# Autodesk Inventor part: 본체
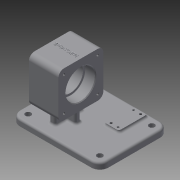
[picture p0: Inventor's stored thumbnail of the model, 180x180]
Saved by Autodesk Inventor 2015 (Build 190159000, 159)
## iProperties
Created: 2019-09
Part Number: 본체
Material: 알루미늄 6061
Document SubType Name: Modeling
Designer: mduedu
Density: 2.71 g/cm^3
Mass: 636.366 g
Surface Area: 520.125 cm^2
Volume: 234.821 cm^3
Appearance: 기본값
Author: mduedu
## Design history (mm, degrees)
sketch "스케치1"
  geometry: L1 (42, -62)-(-84, -62); L2 (-84, -62)-(-84, 36); L3 (-84, 36)-(42, 36); L4 (42, 36)-(42, -62); 1 further point
  constraints: 8 end point, 2 parallel, 1 horizontal, 1 perpendicular
  dimensions: "d0" = 36 distance from line of L3 point (0, 0); "d1" = 98 distance of L1.end L2.end; "d2" = 42 distance from line of L4 point (0, 0); "d3" = 126 distance of L2.end L3.end
extrude "돌출1" new body sketch "스케치1" distance "d4" = 9; taper "d5" = 0 deg
sketch "스케치2"
  geometry: L1 (0, -62)-(0, 36) reference; L2 (27, -32)-(91, -32); L3 (91, -32)-(91, 32); L4 (91, 32)-(27, 32); L5 (27, 32)-(27, -32); L6 (27, -32)-(91, 32); L7 (91, -32)-(27, 32); 3 further points
  constraints: 12 end point, 3 midpoint, 2 parallel, 1 horizontal, 1 horizontal alignment, 1 perpendicular
  dimensions: "d87" = 64 distance of L4.end L3.end; "d88" = 64 distance of L3.end L2.end; "d89" = 59 distance from line of point (59, 0) L1
extrude "돌출2" join sketch "스케치2" stored distance "d8" = 42; taper "d9" = 0 deg
sketch "스케치3"
  geometry: L1 (-17, 4)-(17, 4); L2 (17, 4)-(17, -4); L3 (17, -4)-(-17, -4); L4 (-17, -4)-(-17, 4); L5 (-4, 20)-(4, 20); L6 (4, 20)-(4, -20); L7 (4, -20)-(-4, -20); L8 (-4, -20)-(-4, 20); 5 further points
  constraints: 16 end point, 4 midpoint, 4 parallel, 2 horizontal, 2 horizontal alignment, 2 perpendicular, 2 vertical alignment
  dimensions: "d10" = 8 distance of L5.start L5.end; "d12" = 8 distance of L1.end L2.end; "d13" = 34 distance of L2.end L3.end; "d14" = 40 distance of L5.end L6.end
extrude "돌출3" join sketch "스케치3" stored distance "d15" = 42; taper "d16" = 0 deg
sketch "스케치4"
  geometry: L1 (-32, 91)-(-32, 27) reference; L2 (32, 91)-(-32, 91) reference; L3 (32, 27)-(32, 91) reference; L4 (-32, 27)-(32, 27) reference; C1 r 21 at (0, 59); 3 further points
  constraints: 2 midpoint, 1 centre point, 1 horizontal alignment, 1 vertical alignment
  dimensions: "d17" = 42 diameter of C1
extrude "돌출4" cut sketch "스케치4" distance "d18" = 15; taper "d19" = 0 deg
hole "구멍1" diameter "d22" = 36; stored, may be unused: countersink angle "d26" = 90 deg, drill point angle "d28" = 118 deg; dims "d20" = 10, "d21" = 10, "d23" = 6, "d24" = 4, "d25" = 2, "d27" = 8
fillet "모깎기1" dims "d29" = 0.3
chamfer "모따기1" distance "d30" = 1; stored, may be unused: second distance "d31" = 2, angle "d32" = 45 deg
fillet "모깎기9" dims "d90" = 8
sketch "스케치11"
  geometry: L1 (-24, 27)-(24, 27) reference; L2 (32, 35)-(32, 83) reference; L3 (24, 91)-(-24, 91) reference; L4 (-32, 83)-(-32, 35) reference; C1 r 22 at (0, 59) reference; A1 r 8 centre (-24, 35) between (-32, 35) and (-24, 27) reference; A2 r 8 centre (24, 35) between (24, 27) and (32, 35) reference; A3 r 8 centre (24, 83) between (32, 83) and (24, 91) reference; A4 r 8 centre (-24, 83) between (-24, 91) and (-32, 83) reference; 5 further points
  constraints: 4 coincident
hole "구멍6" sketch "스케치11" at (-24, 83), (24, 83), (24, 35), (-24, 35) diameter "d91" = 3.242; stored, may be unused: countersink angle "d95" = 90 deg, drill point angle "d97" = 118 deg; dims "d92" = 8, "d93" = 4, "d94" = 2, "d96" = 10
fillet "모깎기2" dims "d44" = 12
sketch "스케치6"
  geometry: L1 (-42, 50)-(-42, -24) reference; L2 (-30, -36)-(72, -36) reference; L3 (84, -24)-(84, 50) reference; L4 (72, 62)-(-30, 62) reference; L5 (17, 4)-(17, -4) reference; L6 (17, -4)-(4, -4) reference; L7 (4, -4)-(4, -20) reference; L8 (4, -20)-(-4, -20) reference; L9 (-4, -20)-(-4, -4) reference; L10 (-4, -4)-(-17, -4) reference; L11 (-17, -4)-(-17, 4) reference; L12 (-17, 4)-(-4, 4) reference; L13 (-4, 4)-(-4, 20) reference; L14 (-4, 20)-(4, 20) reference; L15 (4, 20)-(4, 4) reference; L16 (4, 4)-(17, 4) reference; A1 r 12 centre (-30, 50) between (-30, 62) and (-42, 50) reference; A2 r 12 centre (-30, -24) between (-42, -24) and (-30, -36) reference; A3 r 12 centre (72, -24) between (72, -36) and (84, -24) reference; A4 r 12 centre (72, 50) between (84, 50) and (72, 62) reference; 5 further points
  constraints: 4 coincident
hole "구멍3" sketch "스케치6" at (-30, 50), (72, 50), (72, -24), (-30, -24) diameter "d45" = 8; stored, may be unused: countersink angle "d49" = 90 deg, drill point angle "d51" = 118 deg; dims "d46" = 8, "d47" = 4, "d48" = 2, "d50" = 10
sketch "스케치7"
  geometry: L1 (38, 57)-(58, 57); L2 (58, 57)-(58, 17); L3 (58, 17)-(38, 17); L4 (38, 17)-(38, 57); L5 (72, 62)-(-30, 62) reference; 3 further points
  constraints: 8 end point, 2 midpoint, 2 parallel, 1 horizontal, 1 perpendicular
  dimensions: "d52" = 48 horizontal distance of point (48, 57) point (0, 0); "d53" = 20 distance of L1.start L1.end; "d54" = 40 distance of L1.end L2.end; "d55" = 25 distance from line of point (38, 37) L5
extrude "돌출5" join sketch "스케치7" distance "d56" = 3; taper "d57" = 0 deg
fillet "모깎기3" dims "d58" = 3
fillet "모깎기4" dims "d59" = 3
fillet "모깎기5" dims "d60" = 3
fillet "모깎기6" dims "d61" = 3
fillet "모깎기7" dims "d62" = 3
fillet "모깎기8" dims "d63" = 3
sketch "스케치8"
  geometry: L1 (72, 62)-(58.317, 62) reference; L2 (84, -24)-(84, 50) reference; C1 r 1.5 at (43, 53); C2 r 1.5 at (53, 21); 1 further point
  constraints: 2 centre point, 1 equal radius
  dimensions: "d64" = 3 diameter of C1; "d65" = 9 distance from line of C1.centre L1; "d66" = 32 vertical distance of C2.centre C1.centre; "d67" = 10 horizontal distance of C2.centre C1.centre; "d68" = 31 distance from line of L2 C2.centre
hole "구멍4" sketch "스케치8" at (43, 53), (53, 21) diameter "d69" = 3; stored, may be unused: countersink angle "d73" = 90 deg, drill point angle "d75" = 118 deg; dims "d70" = 8, "d71" = 4, "d72" = 2, "d74" = 6
sketch "스케치9"
  geometry: C1 r 1.5 at (43, 53) reference; C2 r 1.5 at (53, 21) reference; 3 further points
  constraints: 2 horizontal alignment, 2 vertical alignment
hole "구멍5" sketch "스케치9" at (53, 53), (43, 21) diameter "d76" = 3.242; stored, may be unused: countersink angle "d80" = 90 deg, drill point angle "d82" = 118 deg; dims "d77" = 6, "d78" = 4, "d79" = 2, "d81" = 8
sketch "스케치10"
  geometry: 2 further points
  constraints: 1 coincident, 1 other
feature "엠보싱1" sketch "스케치10" dims "d0" = 36, "d1" = 98, "d2" = 42, "d3" = 126, "d12" = 8, "d13" = 34, "d85" = 0.5, "d86" = 0
node "솔리드1"
mirror "대칭1"
mirror "대칭2"
node "투영된 루프1"
node "투영된 루프2"
